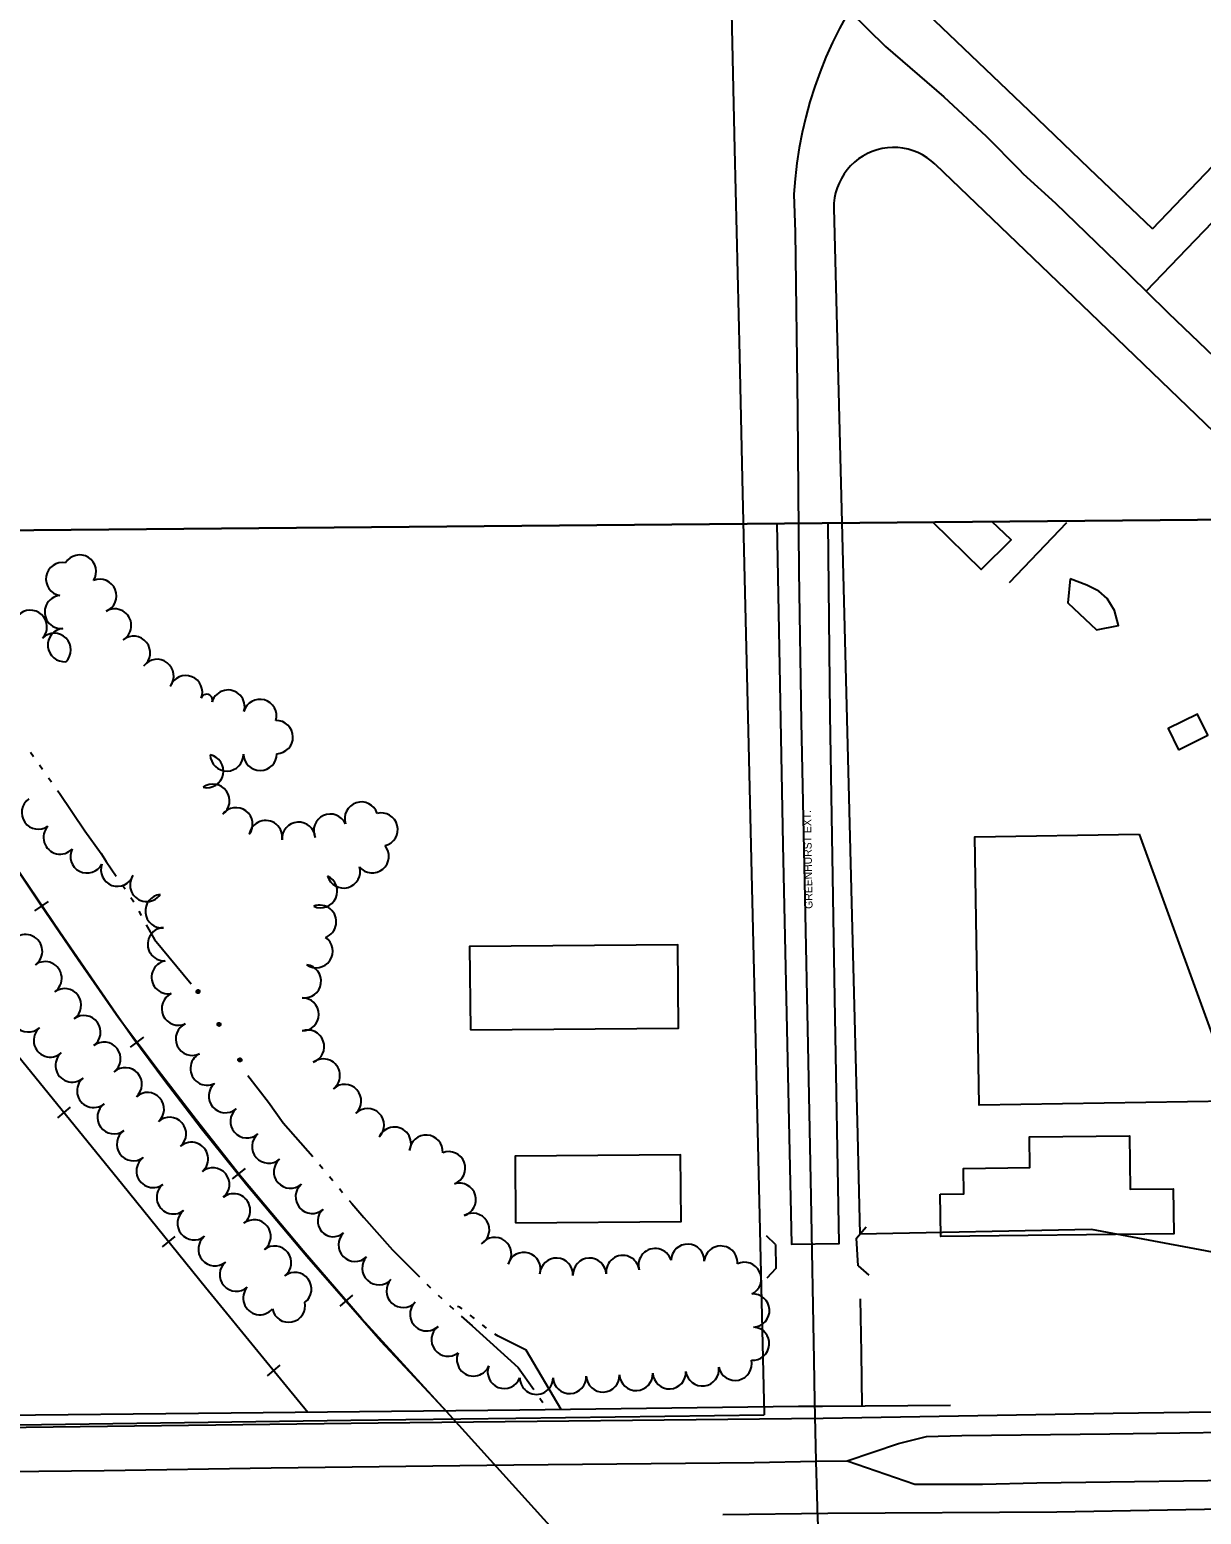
# Model space of a CAD drawing. Extents: x -2233 to 187241, y 4582 to 150524.
# Drawn here: x 118146 to 118851, y 59523 to 60416 of the extents above; entities that cross this region are included whole.
import ezdxf

# ---------------------------------------------------------------- set-up
doc = ezdxf.new("R2010")
doc.units = 0
for name, color, linetype in [('60', 7, 'Continuous'), ('BLDG', 7, 'Continuous'), ('BRIDGE', 7, 'Continuous'), ('CULVERT', 7, 'Continuous'), ('GE_X_CL_2000', 7, 'Continuous'), ('GRID', 7, 'Continuous'), ('RD_X_RR_1', 7, 'Continuous'), ('ROAD', 7, 'Continuous'), ('ROAD-NAME', 7, 'Continuous'), ('RR', 7, 'Continuous'), ('RW_X_Fee_RW', 7, 'Continuous'), ('TREES', 7, 'Continuous'), ('WALL', 7, 'Continuous'), ('WATER', 7, 'Continuous')]:
    doc.layers.add(name, color=color, linetype=linetype)

msp = doc.modelspace()

# ---------------------------------------------------------------- linework, layer by layer
at = {"layer": '60'}
msp.add_line((114990.89, 60087.23), (119990.7, 60130.86), dxfattribs=at)
at = {"layer": 'BLDG'}
msp.add_lwpolyline([(118689.16, 60119.5), (118718.25, 60091.08), (118736.33, 60108.92), (118724.72, 60119.81)], dxfattribs=at)
for points in [[(118771.85, 60085.42), (118770.38, 60071.01), (118787.72, 60054.76), (118800.9, 60057.27), (118798.42, 60066.45), (118793.96, 60073.61), (118789.12, 60077.97), (118781.89, 60081.51)], [(118836.89, 59982.66), (118854.64, 59991.33), (118848.44, 60004.03), (118830.68, 59995.34)], [(118813.35, 59931.75), (118867.25, 59783.63), (118867.45, 59771.2), (118717.01, 59768.77), (118714.41, 59930.14)], [(118411.01, 59814.06), (118536.2, 59815.16), (118535.76, 59865.35), (118410.57, 59864.26)], [(118693.64, 59715.31), (118707.9, 59715.47), (118707.72, 59730.79), (118747.57, 59731.26), (118747.35, 59749.71), (118807.53, 59750.41), (118807.9, 59718.29), (118833.82, 59718.6), (118834.13, 59691.55), (118693.94, 59689.93)], [(118438.22, 59698.1), (118537.82, 59698.96), (118537.47, 59738.96), (118437.87, 59738.09)]]:
    msp.add_lwpolyline(points, close=True, dxfattribs=at)
at = {"layer": 'BRIDGE'}
msp.add_lwpolyline([(117833.26, 59578), (117956.93, 59580.37), (118109.94, 59582.11), (118267.2, 59583.72), (118440.67, 59585.53), (118608.3, 59587.74), (118622.91, 59587.79), (118699.88, 59588.45)], dxfattribs=at)
at = {"layer": 'CULVERT'}
for p, q in [((118643.3, 59688.84), (118649.16, 59695.6)), ((118594.54, 59685.06), (118589.16, 59690.34)), ((118594.54, 59685.06), (118594.67, 59670.52)), ((118644.25, 59672.29), (118643.3, 59688.84)), ((118594.67, 59670.52), (118589.25, 59664.85)), ((118644.25, 59672.29), (118650.66, 59666.58))]:
    msp.add_line(p, q, dxfattribs=at)
at = {"layer": 'GE_X_CL_2000'}
for points in [[(119235.43, 60692.83), (119220.53, 60677.15), (119173.56, 60629.22), (119139.61, 60592.74), (119118.01, 60570.37), (119101.77, 60553.84), (119073.83, 60524.82), (119051.34, 60500.06), (119026.62, 60475.37), (119004.25, 60450.8), (118973.2, 60417.73), (118950.05, 60394.71), (118929.8, 60375.65), (118907.42, 60351.18), (118887.94, 60331.55), (118883.24, 60326.82), (118841.69, 60283.74), (118817.59, 60258.35)], [(118638.85, 60426.98), (118633.03, 60416.47), (118628.81, 60407.95), (118624.92, 60399.25), (118621.37, 60390.41), (118618.16, 60381.44), (118615.29, 60372.36), (118612.79, 60363.18), (118610.64, 60353.94), (118608.85, 60344.65), (118607.42, 60335.34), (118606.99, 60331.55), (118606.35, 60326.02), (118605.64, 60316.71), (118606.37, 60293.94), (118607.72, 60186.01), (118608.52, 60090.31), (118610.03, 59999.17), (118612.26, 59893.47), (118613.95, 59804.92), (118615.82, 59713.69), (118617.69, 59615.42), (118617.95, 59590.9), (118618.87, 59554.62)], [(118638.85, 60426.98), (118660.72, 60405.59), (118695.78, 60375.28), (118721.17, 60351.63), (118741.16, 60331.55), (118743.58, 60329.11), (118763.01, 60311.46), (118799.74, 60275.93), (118817.59, 60258.35)], [(118817.59, 60258.35), (118830.85, 60245.29), (118871.74, 60206.02), (118912.64, 60167.79), (118955.61, 60126.66), (118989.53, 60093.62), (119021.57, 60062.87)], [(118637.67, 59554.95), (118668.58, 59565.35), (118685.39, 59569.6), (118706.63, 59570.08), (118795.64, 59571.17), (118908.13, 59572.68), (119026.62, 59574.51), (119143.63, 59576.52), (119266.31, 59577.76)], [(117089.46, 59534.61), (117188.13, 59535.82), (117286.59, 59537.3), (117403.02, 59538.61), (117495.02, 59539.89), (117597.94, 59541.18), (117683.75, 59542.64), (117758.76, 59543.31), (117864.38, 59544.34), (117977.18, 59546.65), (118072.64, 59547.94), (118190.66, 59549.1), (118291.12, 59550.63), (118437.23, 59552.52), (118581.72, 59553.96), (118618.87, 59554.62), (118637.67, 59554.95)], [(118618.87, 59554.62), (118619.73, 59520.17), (118621.82, 59480.39), (118622.09, 59471.61), (118622.15, 59462.82), (118621.99, 59454.04), (118621.63, 59445.26), (118621.05, 59436.49), (118620.27, 59427.74), (118619.27, 59419.01), (118618.07, 59410.3), (118616.65, 59401.63), (118615.03, 59392.99), (118613.2, 59384.4), (118611.16, 59375.85), (118608.92, 59367.35), (118600.55, 59339.33)], [(118637.67, 59554.95), (118678.45, 59540.96), (118719.03, 59540.89), (118751.77, 59541.72), (118898.61, 59543.75)]]:
    msp.add_lwpolyline(points, dxfattribs=at)
at = {"layer": 'GRID'}
msp.add_line((119990.7, 60130.86), (114990.89, 60087.23), dxfattribs=at)
at = {"layer": 'RD_X_RR_1'}
msp.add_line((118459.01, 59515.55), (118394.78, 59586.51), dxfattribs=at)
msp.add_lwpolyline([(118394.78, 59586.51), (118357.1, 59626.91), (118312.56, 59677.88), (118276.65, 59720.71), (118249.35, 59754.54), (118226.94, 59783.61), (118207.93, 59809.37), (118197.74, 59824.01), (118164.06, 59872.82), (118122.36, 59934.31), (118083.44, 59993.01), (118041.81, 60056.46), (117996.72, 60124.86), (117951.01, 60194.76), (117916.1, 60246.88), (117861.06, 60328.58), (117808.14, 60404.05), (117772.42, 60455.48)], dxfattribs=at)
at = {"layer": 'ROAD'}
for points in [[(118595.25, 60118.68), (118599.03, 59925.53), (118604.21, 59685.2), (118632.83, 59685.61), (118630.33, 59833.17), (118627.39, 60003.88), (118626.29, 60118.95)], [(118623.26, 59580.48), (118355.65, 59577.62), (118078.39, 59574.19), (117878.65, 59571.35), (117803.66, 59570.9), (117619.09, 59569.05), (117509.81, 59566.76), (117408.79, 59565.81), (117307.15, 59564.45), (117189.55, 59562.84)], [(118950.16, 59585.34), (118797.7, 59583.3), (118623.26, 59580.48)], [(118626.02, 59523.37), (118763.69, 59524.18), (118896.98, 59526.73)], [(118562.94, 59522.68), (118626.02, 59523.37)]]:
    msp.add_lwpolyline(points, dxfattribs=at)
at = {"layer": 'RR'}
for p, q in [((118157.14, 59891.33), (118148.87, 59885.7)), ((118214.45, 59809.71), (118206.47, 59803.67)), ((118162.79, 59761.25), (118170.55, 59767.55)), ((118275.6, 59730.7), (118267.73, 59724.52)), ((118225.76, 59683.58), (118233.53, 59689.87)), ((118340.06, 59654.56), (118332.49, 59648.02)), ((118288.94, 59606.04), (118296.68, 59612.37))]:
    msp.add_line(p, q, dxfattribs=at)
for points in [[(117881.45, 60112.45), (117997.02, 59974.41), (118075.06, 59877.94), (118136.09, 59802.09), (118201.98, 59720.89), (118251.79, 59659.38), (118286.87, 59616.47), (118300.45, 59599.86), (118313.31, 59584.2)], [(118396.23, 59585.07), (118345.59, 59640.53), (118310.39, 59681.21), (118272.77, 59726.19), (118246.15, 59760.06), (118223.28, 59789.74), (118199.41, 59821.29), (118175.03, 59856.17), (118152.56, 59889.16), (118129.26, 59924.28), (118099.06, 59969.25), (118058.33, 60032.69), (118004.83, 60113.53)]]:
    msp.add_lwpolyline(points, dxfattribs=at)
at = {"layer": 'RW_X_Fee_RW'}
for p in [(118643.79, 59751.17), (118784.6, 59694.07)]:
    msp.add_line(p, (118645.19, 59691.17), dxfattribs=at)
for points in [[(118821.23, 60295.97), (118907.65, 60386.25), (118924.96, 60404.34), (118942.23, 60422.37), (118959.54, 60440.46), (118990.64, 60472.96), (118994.12, 60476.58), (119011.43, 60494.67), (119039.06, 60523.54), (119045.96, 60530.74), (119080.54, 60566.87), (119115.11, 60602.99), (119166.95, 60657.15), (119201.53, 60693.27)], [(118567.43, 60453.28), (118569.98, 60343.75), (118572.87, 60219.58), (118574.59, 60145.58), (118575.99, 60085.58), (118578.32, 59985.58), (118580.12, 59907.98), (118582.45, 59807.98), (118582.92, 59787.98), (118584.31, 59727.98), (118586.11, 59650.7), (118587.7, 59582.58)], [(118821.23, 60295.97), (118783.31, 60332.25), (118747.18, 60366.82), (118672.93, 60437.87)], [(118690.62, 60334.82), (118688.22, 60336.87), (118685.72, 60338.67), (118683.02, 60340.37), (118680.22, 60341.77), (118677.32, 60342.87), (118674.32, 60343.77), (118671.22, 60344.37), (118668.12, 60344.77), (118665.02, 60344.87), (118661.82, 60344.67), (118658.72, 60344.17), (118655.72, 60343.47), (118652.72, 60342.47), (118649.82, 60341.17), (118647.12, 60339.68), (118644.52, 60337.98), (118642.02, 60335.98), (118639.72, 60333.88), (118637.72, 60331.48), (118635.82, 60328.98), (118634.22, 60326.28), (118632.82, 60323.48), (118631.62, 60320.58), (118630.72, 60317.58), (118630.12, 60314.48), (118629.72, 60311.38), (118629.62, 60308.28)], [(118690.62, 60334.82), (118734.73, 60292.48), (118783.73, 60245.38), (118821.1, 60209.45), (118921.7, 60112.75), (118975.49, 60061.05), (119018.78, 60019.44), (119089.81, 59951.16)], [(118629.62, 60308.28), (118640.44, 59882.87), (118643.79, 59751.17)], [(118966.3, 59659.76), (118850, 59681.77), (118784.6, 59694.07)], [(117891.1, 59573.4), (117895.43, 59573.16), (118339.2, 59579.3), (118438.3, 59580.61), (118587.7, 59582.58)]]:
    msp.add_lwpolyline(points, dxfattribs=at)
at = {"layer": 'TREES'}
for centre, radius, start, end in [((118175.93, 60089.79), 10, 327.85089, 147.85089), ((118165.74, 60085.26), 10, 80.07516, 260.07516), ((118188.17, 60075.2), 10, 292.17976, 112.17976), ((118164.97, 60065.45), 10, 95.47079, 275.47079), ((118146.35, 60056.57), 10, 317.20681, 137.20681), ((118197.07, 60057.36), 10, 300.86364, 120.86364), ((118160.73, 60042.68), 10, 314.7905, 134.7905), ((118166.85, 60045.54), 10, 95.3198, 275.3198), ((118208.41, 60040.94), 10, 308.36992, 128.36992), ((118222.57, 60027.02), 10, 322.62114, 142.62114), ((118239.8, 60017.26), 10, 338.33307, 158.33307), ((118252.4, 60012.55), 3.46, 342.86061, 162.86061), ((118265.26, 60008.58), 10, 342.86061, 162.86061), ((118284.45, 60002.94), 10, 344.32723, 164.32723), ((118294.31, 59990.24), 10, 271.34928, 91.34928), ((118264.55, 59979.78), 10, 181.13724, 1.13724), ((118284.55, 59980.11), 10, 180.76378, 0.76378), ((118252.46, 59969.8), 10, 257.91554, 77.91554), ((118256.2, 59951.9), 10, 305.70568, 125.70568), ((118151.17, 59944.83), 10, 125.17143, 305.17143), ((118270.04, 59937.78), 10, 323.10449, 143.10449), ((118326.79, 59933.94), 10, 24.71409, 204.71409), ((118345.38, 59941.22), 10, 18.09871, 198.09871), ((118357.31, 59934.63), 10, 284.03665, 104.03665), ((118164.25, 59929.85), 10, 137.07251, 317.07251), ((118287.89, 59930.09), 10, 350.32552, 170.32552), ((118307.73, 59929.08), 10, 3.85724, 183.85724), ((118180.46, 59918.46), 10, 152.75333, 332.75333), ((118352.03, 59918.55), 10, 219.63905, 39.63905), ((118198.75, 59910.46), 10, 160.00975, 340.00975), ((118334.72, 59909.42), 10, 195.97484, 15.97484), ((118216.31, 59901.26), 10, 144.70841, 324.70841), ((118320.96, 59897.56), 10, 245.53891, 65.53891), ((118225.46, 59885.53), 10, 95.63773, 275.63773), ((118320.38, 59879.11), 10, 290.83382, 110.83383), ((118226.92, 59865.59), 10, 92.75542, 272.75542), ((118143.58, 59861.45), 10, 305.63093, 125.63093), ((118318.28, 59861.52), 10, 235.56639, 55.56639), ((118155.23, 59845.19), 10, 305.63093, 125.63093), ((118229.25, 59845.78), 10, 100.67628, 280.67628), ((118311.23, 59843.37), 10, 261.98286, 81.98286), ((118166.91, 59828.96), 10, 305.8299, 125.8299), ((118145.19, 59822.83), 10, 131.27587, 311.27587), ((118235.33, 59826.89), 10, 115.01514, 295.01514), ((118309.8, 59823.47), 10, 269.80949, 89.80949), ((118178.62, 59812.74), 10, 305.82992, 125.82992), ((118158.35, 59807.77), 10, 131.02738, 311.02738), ((118243.79, 59808.77), 10, 115.01514, 295.01514), ((118313.13, 59804.05), 10, 289.63425, 109.63425), ((118190.62, 59796.75), 10, 307.96994, 127.96994), ((118171.47, 59792.68), 10, 130.97037, 310.97037), ((118252.61, 59790.82), 10, 117.30533, 297.30533), ((118322.57, 59786.69), 10, 307.45944, 127.45944), ((118184.4, 59777.42), 10, 129.59266, 309.59266), ((118203.44, 59781.41), 10, 311.76884, 131.76884), ((118216.76, 59766.49), 10, 311.76884, 131.76884), ((118263.63, 59774.28), 10, 130.07346, 310.07346), ((118335.37, 59771.35), 10, 312.22286, 132.22286), ((118196.63, 59761.61), 10, 125.85722, 305.85722), ((118276.62, 59759.07), 10, 130.89337, 310.89337), ((118349.14, 59756.85), 10, 314.82112, 134.82112), ((118230.08, 59751.58), 10, 311.76884, 131.76884), ((118208.34, 59745.4), 10, 125.85722, 305.85722), ((118289.71, 59743.95), 10, 130.89337, 310.89337), ((118365.31, 59745.66), 10, 335.77761, 155.77761), ((118384.41, 59740.9), 10, 356.22851, 176.22851), ((118243.27, 59736.54), 10, 310.70975, 130.70975), ((118397.97, 59730.9), 10, 290.96221, 110.96221), ((118220.15, 59729.26), 10, 126.49646, 306.49646), ((118256.1, 59721.2), 10, 309.15546, 129.15546), ((118302.8, 59728.83), 10, 130.89337, 310.89337), ((118232.32, 59713.39), 10, 128.46289, 308.46289), ((118315.89, 59713.71), 10, 130.89337, 310.89337), ((118404.39, 59711.97), 10, 286.51007, 106.51007), ((118268.63, 59705.61), 10, 308.38982, 128.38983), ((118244.8, 59697.76), 10, 128.75872, 308.75872), ((118328.57, 59699.07), 9.37, 130.89337, 310.89337), ((118412.47, 59693.87), 10, 301.62191, 121.62191), ((118280.98, 59689.88), 10, 307.90951, 127.90951), ((118257.38, 59682.22), 10, 129.20601, 309.20601), ((118341.66, 59684.81), 10, 134.05931, 314.05931), ((118425.69, 59679.33), 10, 322.92895, 142.92895), ((118541.69, 59675.27), 10, 358.25281, 178.25281), ((118293.27, 59674.1), 10, 307.90946, 127.90946), ((118355.92, 59670.79), 10, 136.94091, 316.94091), ((118443.21, 59670.31), 10, 342.60691, 162.60691), ((118462.75, 59666.9), 10, 357.56759, 177.56759), ((118482.73, 59666.89), 10, 2.42307, 182.42307), ((118502.65, 59668.51), 10, 6.85909, 186.85909), ((118522.14, 59672.64), 10, 17.07918, 197.07918), ((118561.65, 59674.15), 10, 355.28809, 175.28809), ((118270.25, 59666.91), 10, 130.90286, 310.90286), ((118305.45, 59658.24), 10, 307.14969, 127.14969), ((118575.98, 59664.33), 10, 295.8337, 115.8337), ((118284.35, 59652.8), 10, 139.04827, 319.04827), ((118370.55, 59657.16), 10, 137.12106, 317.12106), ((118301.7, 59648.26), 10, 191.62324, 11.62324), ((118384.71, 59643.06), 10, 133.09794, 313.09794), ((118580.96, 59645.35), 10, 273.57848, 93.57848), ((118397.61, 59627.8), 10, 127.32191, 307.32191), ((118580.82, 59625.39), 10, 265.59861, 85.59861), ((118412.87, 59615.93), 10, 156.90782, 336.90782), ((118570.28, 59613.3), 10, 192.28573, 12.28573), ((118431.39, 59608.39), 10, 158.80525, 338.80525), ((118450.72, 59604.85), 10, 180.43758, 0.43758), ((118470.71, 59605.38), 10, 182.5826, 2.5826), ((118480.71, 59605.83), 0.0161, 182.58294, 2.58294), ((118490.72, 59606.28), 10, 182.5826, 2.5826), ((118510.7, 59607.18), 10, 182.58337, 2.58337), ((118530.67, 59608.17), 10, 183.06557, 3.06557), ((118550.58, 59609.93), 10, 187.08302, 7.08302)]:
    msp.add_arc(centre, radius, start, end, dxfattribs=at)
at = {"layer": 'WALL'}
msp.add_line((118769.64, 60119.14), (118735.08, 60082.97), dxfattribs=at)
msp.add_lwpolyline([(118646.59, 59588), (118646.31, 59619.91), (118645.63, 59652.3)], dxfattribs=at)
at = {"layer": 'WATER'}
for p, q in [((118146.48, 59981.13), (118148.27, 59978.58)), ((118151.88, 59973.48), (118153.68, 59970.92)), ((118157.28, 59965.81), (118159.09, 59963.26)), ((118201.57, 59901.46), (118203.32, 59898.87)), ((118211.52, 59885.59), (118213.03, 59882.86)), ((118320.3, 59733.24), (118322.28, 59730.83)), ((118326.25, 59726), (118328.23, 59723.58)), ((118332.21, 59718.75), (118334.19, 59716.34)), ((118384.87, 59661.12), (118387.08, 59658.91)), ((118391.61, 59654.61), (118393.93, 59652.51)), ((118398.55, 59648.32), (118400.87, 59646.22)), ((118413.41, 59640.61), (118410.96, 59642.55)), ((118420.76, 59634.8), (118418.31, 59636.74)), ((118452.77, 59592.64), (118454.56, 59590.07))]:
    msp.add_line(p, q, dxfattribs=at)
for points in [[(118162.69, 59958.15), (118163.86, 59956.49), (118179.19, 59933.79), (118188.94, 59920.13), (118192.01, 59915.49), (118198.05, 59906.62)], [(118206.83, 59893.7), (118208.17, 59891.75), (118208.54, 59891.08)], [(118216.02, 59877.36), (118220.93, 59868.39), (118243.02, 59841.89)], [(118277.13, 59786.66), (118289.64, 59770.6), (118298.31, 59758.31), (118316.28, 59738.02)], [(118338.16, 59711.51), (118339.64, 59709.7), (118346.86, 59701.2), (118364.16, 59681.85), (118380.45, 59665.54)], [(118406.06, 59646.42), (118404.77, 59647.44), (118403.31, 59647.71)], [(118405.51, 59642.03), (118412.02, 59636.12), (118439.83, 59611.14), (118449.19, 59597.76)], [(118465.62, 59585.86), (118444.66, 59621.44), (118427.69, 59629.94), (118425.77, 59631.07)]]:
    msp.add_lwpolyline(points, dxfattribs=at)
for points in [[(118247.2, 59837.1), (118247.18, 59837.19), (118247.18, 59837.19), (118247.18, 59837.19), (118247.19, 59837.19), (118247.19, 59837.19), (118247.2, 59837.19), (118247.19, 59837.19), (118247.18, 59837.11), (118246.19, 59837.28), (118246.24, 59837.54), (118246.43, 59837.88), (118246.75, 59838.11), (118247.15, 59838.21), (118247.54, 59838.15), (118247.88, 59837.93), (118248.12, 59837.6), (118248.18, 59837.31)], [(118247.18, 59837.3), (118247.2, 59837.2), (118247.19, 59837.21), (118247.19, 59837.21), (118247.19, 59837.21), (118247.18, 59837.21), (118247.18, 59837.2), (118247.18, 59837.21), (118247.19, 59837.28), (118248.18, 59837.12), (118248.14, 59836.87), (118247.94, 59836.53), (118247.62, 59836.29), (118247.23, 59836.19), (118246.83, 59836.26), (118246.48, 59836.47), (118246.26, 59836.8), (118246.2, 59837.1)], [(118259.81, 59817.35), (118259.79, 59817.45), (118259.79, 59817.44), (118259.79, 59817.44), (118259.8, 59817.44), (118259.8, 59817.44), (118259.8, 59817.44), (118259.8, 59817.44), (118259.79, 59817.37), (118258.8, 59817.52), (118258.85, 59817.78), (118259.05, 59818.13), (118259.36, 59818.37), (118259.75, 59818.46), (118260.15, 59818.4), (118260.5, 59818.18), (118260.73, 59817.85), (118260.79, 59817.56)], [(118259.79, 59817.55), (118259.8, 59817.45), (118259.8, 59817.46), (118259.8, 59817.46), (118259.79, 59817.46), (118259.79, 59817.46), (118259.79, 59817.46), (118259.79, 59817.46), (118259.8, 59817.53), (118260.79, 59817.38), (118260.74, 59817.12), (118260.55, 59816.78), (118260.23, 59816.54), (118259.84, 59816.44), (118259.44, 59816.51), (118259.1, 59816.72), (118258.87, 59817.06), (118258.81, 59817.34)], [(118272.36, 59795.96), (118272.34, 59796.05), (118272.34, 59796.05), (118272.35, 59796.05), (118272.35, 59796.04), (118272.36, 59796.05), (118272.36, 59796.05), (118272.36, 59796.04), (118272.34, 59795.97), (118271.36, 59796.13), (118271.4, 59796.39), (118271.59, 59796.73), (118271.92, 59796.97), (118272.31, 59797.06), (118272.71, 59797.01), (118273.04, 59796.79), (118273.28, 59796.46), (118273.34, 59796.16)], [(118272.34, 59796.15), (118272.36, 59796.06), (118272.36, 59796.06), (118272.36, 59796.06), (118272.35, 59796.06), (118272.35, 59796.06), (118272.34, 59796.06), (118272.35, 59796.07), (118272.36, 59796.14), (118273.34, 59795.98), (118273.3, 59795.72), (118273.1, 59795.39), (118272.78, 59795.15), (118272.39, 59795.05), (118272, 59795.11), (118271.65, 59795.33), (118271.42, 59795.65), (118271.36, 59795.95)]]:
    msp.add_lwpolyline(points, close=True, dxfattribs=at)

# ---------------------------------------------------------------- texts
at = {"layer": 'ROAD-NAME'}
msp.add_text('GREENHURST EXT.', height=4.68, rotation=90.91518, dxfattribs=at).set_placement((118616.86, 59886.96))

doc.saveas('drawing.dxf')
